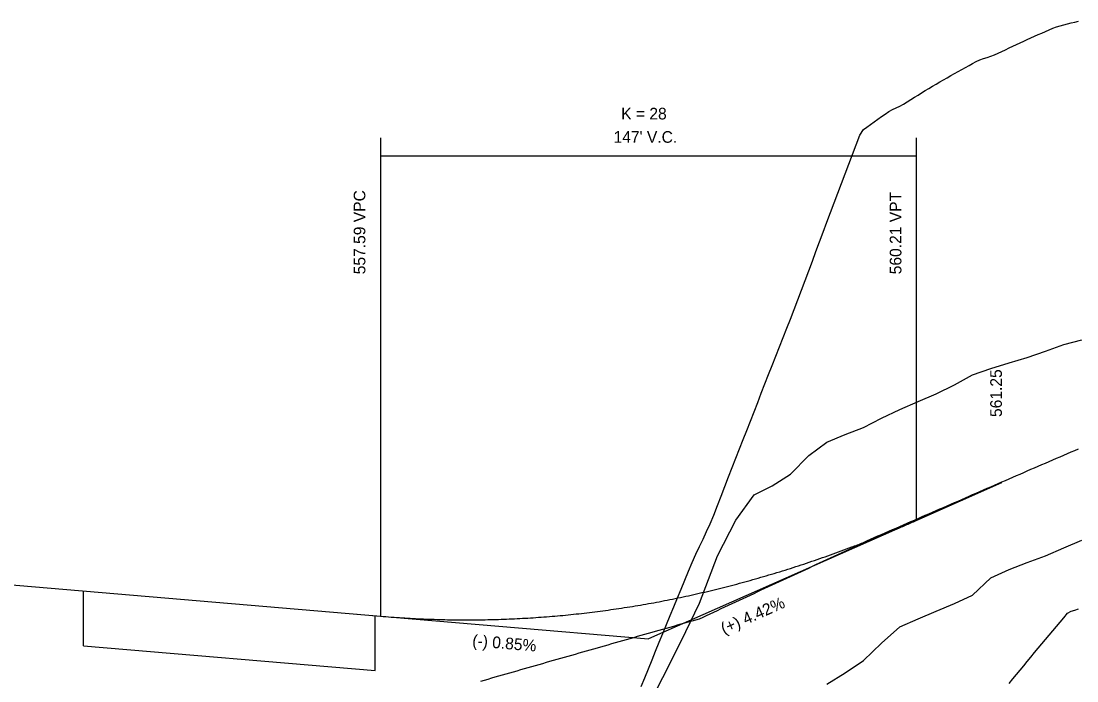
# Model space of a CAD drawing. Extents: x 1733571 to 1737171, y 1214895 to 1219895.
# Drawn here: x 1735360.8 to 1735650.6, y 1217953.6 to 1218134.6 of the extents above; entities that cross this region are included whole.
import ezdxf

# ---------------------------------------------------------------- set-up
doc = ezdxf.new("R2010")
doc.units = 0
for name, color, linetype in [('RD_DDB_GradeTX', 7, 'Continuous'), ('RD_DDB_Profile_EX', 7, 'Continuous'), ('RD_DDB_Profile_Lbl', 7, 'Continuous'), ('RD_DDB_Profile_PR', 7, 'Continuous'), ('RD_DDB_StripGrade', 7, 'Continuous'), ('RD_DDB_VCLbl', 7, 'Continuous'), ('RD_PD_Bridge', 7, 'Continuous'), ('RD_Sketch1', 7, 'Continuous'), ('RD_Sketch2', 7, 'Continuous'), ('RD_Sketch3', 7, 'Continuous'), ('RD_Sketch4', 7, 'Continuous')]:
    doc.layers.add(name, color=color, linetype=linetype)

msp = doc.modelspace()

# ---------------------------------------------------------------- linework, layer by layer
at = {"layer": 'RD_DDB_GradeTX'}
for p in [(1735608.3751, 1217998.43559), (1735450.90416, 1217972.09558)]:
    msp.add_line(p, (1735533.0087, 1217965.12394), dxfattribs=at)
at = {"layer": 'RD_DDB_Profile_EX'}
for points in [[(1735603.9887, 1217996.85951), (1735604.9887, 1217997.29438), (1735605.9887, 1217997.72923), (1735606.9887, 1217998.16405), (1735607.9887, 1217998.59884), (1735608.9887, 1217999.03361), (1735609.9887, 1217999.46835), (1735610.9887, 1217999.90307), (1735611.9887, 1218000.33775), (1735612.9887, 1218000.77242), (1735613.9887, 1218001.20705), (1735614.9887, 1218001.64166), (1735615.9887, 1218002.07624), (1735616.9887, 1218002.5108), (1735617.9887, 1218002.94533), (1735618.9887, 1218003.37983), (1735619.9887, 1218003.83148), (1735620.9887, 1218004.28324), (1735621.9887, 1218004.71734), (1735622.9887, 1218005.15135), (1735623.9887, 1218005.58528), (1735624.9887, 1218006.01911), (1735625.9887, 1218006.45286), (1735626.9887, 1218006.88651), (1735627.9887, 1218007.32008), (1735628.9887, 1218007.75356), (1735629.9887, 1218008.18695), (1735630.9887, 1218008.62024), (1735631.9887, 1218009.05345), (1735632.9887, 1218009.48657), (1735633.9887, 1218009.91959), (1735634.9887, 1218010.35253), (1735635.9887, 1218010.78538), (1735636.9887, 1218011.21813), (1735637.9887, 1218011.6508), (1735638.9887, 1218012.08337), (1735639.9887, 1218012.51585), (1735640.9887, 1218012.94824), (1735641.9887, 1218013.38054), (1735642.9887, 1218013.81275), (1735643.9887, 1218014.24487), (1735644.9887, 1218014.67689), (1735645.9887, 1218015.11698), (1735646.9887, 1218015.54701), (1735647.9887, 1218015.97849), (1735648.9887, 1218016.41013), (1735649.9887, 1218016.84161), (1735650.9887, 1218017.27294)], [(1735503.9887, 1217958.42449), (1735504.9887, 1217958.70923), (1735505.9887, 1217958.99392), (1735506.9887, 1217959.27855), (1735507.9887, 1217959.56313), (1735508.9887, 1217959.84766), (1735509.9887, 1217960.13213), (1735510.9887, 1217960.41655), (1735511.9887, 1217960.70091), (1735512.9887, 1217960.98522), (1735513.9887, 1217961.26948), (1735514.9887, 1217961.55368), (1735515.9887, 1217961.83783), (1735516.9887, 1217962.12193), (1735517.9887, 1217962.40597), (1735518.9887, 1217962.68995), (1735519.9887, 1217962.97388), (1735520.9887, 1217963.25776), (1735521.9887, 1217963.54927), (1735522.9887, 1217963.8496), (1735523.9887, 1217964.14087), (1735524.9887, 1217964.42442), (1735525.9887, 1217964.70789), (1735526.9887, 1217964.99128), (1735527.9887, 1217965.27459), (1735528.9887, 1217965.55782), (1735529.9887, 1217965.84097), (1735530.9887, 1217966.12404), (1735531.9887, 1217966.40703), (1735532.9887, 1217966.68993), (1735533.9887, 1217966.97276), (1735534.9887, 1217967.2555), (1735535.9887, 1217967.53816), (1735536.9887, 1217967.82074), (1735537.9887, 1217968.10324), (1735538.9887, 1217968.38565), (1735539.9887, 1217968.66799), (1735540.9887, 1217968.95024), (1735541.9887, 1217969.23241), (1735542.9887, 1217969.5145), (1735543.9887, 1217969.79651), (1735544.9887, 1217970.07843), (1735545.9887, 1217970.36027), (1735546.9887, 1217970.64295), (1735547.9887, 1217971.10173), (1735548.9887, 1217971.56844), (1735549.9887, 1217972.03507), (1735550.9887, 1217972.50163), (1735551.9887, 1217972.96811), (1735552.9887, 1217973.43451), (1735553.9887, 1217973.90084), (1735554.9887, 1217974.36709), (1735555.9887, 1217974.83326), (1735556.9887, 1217975.29936), (1735557.9887, 1217975.76537), (1735558.9887, 1217976.23131), (1735559.9887, 1217976.69717), (1735560.9887, 1217977.16296), (1735561.9887, 1217977.62866), (1735562.9887, 1217978.09429), (1735563.9887, 1217978.55984), (1735564.9887, 1217979.02531), (1735565.9887, 1217979.4907), (1735566.9887, 1217979.95601), (1735567.9887, 1217980.42125), (1735568.9887, 1217980.8864), (1735569.9887, 1217981.35148), (1735570.9887, 1217981.80865), (1735571.9887, 1217982.25444), (1735572.9887, 1217982.71922), (1735573.9887, 1217983.18437), (1735574.9887, 1217983.64948), (1735575.9887, 1217984.11454), (1735576.9887, 1217984.57955), (1735577.9887, 1217985.04451), (1735578.9887, 1217985.50941), (1735579.9887, 1217985.97427), (1735580.9887, 1217986.43908), (1735581.9887, 1217986.90383), (1735582.9887, 1217987.36853), (1735583.9887, 1217987.83319), (1735584.9887, 1217988.29779), (1735585.9887, 1217988.76234), (1735586.9887, 1217989.22684), (1735587.9887, 1217989.69128), (1735588.9887, 1217990.15568), (1735589.9887, 1217990.62002), (1735590.9887, 1217991.08431), (1735591.9887, 1217991.54855), (1735592.9887, 1217992.01274), (1735593.9887, 1217992.47687), (1735594.9887, 1217992.93966), (1735595.9887, 1217993.37963), (1735596.9887, 1217993.8147), (1735597.9887, 1217994.24975), (1735598.9887, 1217994.68477), (1735599.9887, 1217995.11977), (1735600.9887, 1217995.55474), (1735601.9887, 1217995.98969), (1735602.9887, 1217996.42461), (1735603.9887, 1217996.85951)], [(1735486.9887, 1217953.55972), (1735487.9887, 1217953.84421), (1735488.9887, 1217954.1287), (1735489.9887, 1217954.41319), (1735490.9887, 1217954.69768), (1735491.9887, 1217954.98217), (1735492.9887, 1217955.26666), (1735493.9887, 1217955.55115), (1735494.9887, 1217955.83564), (1735495.9887, 1217956.12013), (1735496.9887, 1217956.41204), (1735497.9887, 1217956.7132), (1735498.9887, 1217956.99999), (1735499.9887, 1217957.28499), (1735500.9887, 1217957.56995), (1735501.9887, 1217957.85485), (1735502.9887, 1217958.13969), (1735503.9887, 1217958.42449)]]:
    msp.add_lwpolyline(points, dxfattribs=at)
at = {"layer": 'RD_DDB_Profile_PR'}
for p, q in [((1735606.5087, 1217997.61065), (1735630.0087, 1218007.99755)), ((1735355.0087, 1217980.23823), (1735459.5087, 1217971.36496))]:
    msp.add_line(p, q, dxfattribs=at)
msp.add_spline([(1735459.5087, 1217971.36496), (1735462.4487, 1217971.13081), (1735465.3887, 1217970.92764), (1735468.3287, 1217970.75545), (1735471.2687, 1217970.61425), (1735474.2087, 1217970.50403), (1735477.1487, 1217970.42479), (1735480.0887, 1217970.37654), (1735483.0287, 1217970.35926), (1735485.9687, 1217970.37297), (1735488.9087, 1217970.41766), (1735491.8487, 1217970.49333), (1735494.7887, 1217970.59999), (1735497.7287, 1217970.73762), (1735500.6687, 1217970.90624), (1735503.6087, 1217971.10584), (1735506.5487, 1217971.33643), (1735509.4887, 1217971.59799), (1735512.4287, 1217971.89054), (1735515.3687, 1217972.21407), (1735518.3087, 1217972.56858), (1735521.2487, 1217972.95407), (1735524.1887, 1217973.37055), (1735527.1287, 1217973.81801), (1735530.0687, 1217974.29645), (1735533.0087, 1217974.80587), (1735535.9487, 1217975.34628), (1735538.8887, 1217975.91766), (1735541.8287, 1217976.52003), (1735544.7687, 1217977.15338), (1735547.7087, 1217977.81772), (1735550.6487, 1217978.51303), (1735553.5887, 1217979.23933), (1735556.5287, 1217979.99661), (1735559.4687, 1217980.78487), (1735562.4087, 1217981.60412), (1735565.3487, 1217982.45435), (1735568.2887, 1217983.33555), (1735571.2287, 1217984.24775), (1735574.1687, 1217985.19092), (1735577.1087, 1217986.16507), (1735580.0487, 1217987.17021), (1735582.9887, 1217988.20633), (1735585.9287, 1217989.27343), (1735588.8687, 1217990.37152), (1735591.8087, 1217991.50058), (1735594.7487, 1217992.66063), (1735597.6887, 1217993.85166), (1735600.6287, 1217995.07367), (1735603.5687, 1217996.32667), (1735606.5087, 1217997.61065)], degree=3, dxfattribs=at)
at = {"layer": 'RD_DDB_VCLbl'}
for p, q in [((1735459.5087, 1218102.61065), (1735459.5087, 1217971.36496)), ((1735606.5087, 1218102.61065), (1735606.5087, 1217997.61065)), ((1735459.5087, 1218097.61065), (1735606.5087, 1218097.61065))]:
    msp.add_line(p, q, dxfattribs=at)
at = {"layer": 'RD_PD_Bridge'}
for p, q in [((1735378.0087, 1217963.23129), (1735378.0087, 1217978.28526)), ((1735458.0087, 1217956.43835), (1735458.0087, 1217971.49232)), ((1735378.0087, 1217963.23129), (1735458.0087, 1217956.43835))]:
    msp.add_line(p, q, dxfattribs=at)
at = {"layer": 'RD_Sketch1'}
for points in [[(1735605.9887, 1218113.71216), (1735606.9887, 1218114.32618), (1735607.9887, 1218114.93548), (1735608.9887, 1218115.54006), (1735609.9887, 1218116.13991), (1735610.9887, 1218116.73504), (1735611.9887, 1218117.32546), (1735612.9887, 1218117.91115), (1735613.9887, 1218118.49211), (1735614.9887, 1218119.06836), (1735615.9887, 1218119.63988), (1735616.9887, 1218120.20669), (1735617.9887, 1218120.76876), (1735618.9887, 1218121.32612), (1735619.9887, 1218121.87875), (1735620.9887, 1218122.42666), (1735621.9887, 1218122.96985), (1735622.9887, 1218123.50831), (1735623.9887, 1218123.9502), (1735624.9887, 1218124.29634), (1735625.9887, 1218124.63774), (1735626.9887, 1218124.97439), (1735627.9887, 1218125.30631), (1735628.9887, 1218125.76265), (1735629.9887, 1218126.25346), (1735630.9887, 1218126.73942), (1735631.9887, 1218127.22053), (1735632.9887, 1218127.6968), (1735633.9887, 1218128.16821), (1735634.9887, 1218128.63478), (1735635.9887, 1218129.0965), (1735636.9887, 1218129.55336), (1735637.9887, 1218130.00538), (1735638.9887, 1218130.45255), (1735639.9887, 1218130.89487), (1735640.9887, 1218131.33234), (1735641.9887, 1218131.76496), (1735642.9887, 1218132.19273), (1735643.9887, 1218132.61565), (1735644.9887, 1218133.03372), (1735645.9887, 1218133.29717), (1735646.9887, 1218133.56553), (1735647.9887, 1218133.82904), (1735648.9887, 1218134.08771), (1735649.9887, 1218134.34152), (1735650.9887, 1218134.59049)], [(1735530.9887, 1217952.05982), (1735531.9887, 1217954.49408), (1735532.9887, 1217956.92808), (1735533.9887, 1217959.36181), (1735534.9887, 1217961.79527), (1735535.9887, 1217964.22846), (1735536.9887, 1217966.66138), (1735537.9887, 1217969.09403), (1735538.9887, 1217971.52641), (1735539.9887, 1217973.95851), (1735540.9887, 1217976.39034), (1735541.9887, 1217978.82189), (1735542.9887, 1217981.25317), (1735543.9887, 1217983.68417), (1735544.9887, 1217986.11489), (1735545.9887, 1217988.36446), (1735546.9887, 1217990.44829), (1735547.9887, 1217992.53127), (1735548.9887, 1217994.61339), (1735549.9887, 1217996.69465), (1735550.9887, 1217999.07523), (1735551.9887, 1218001.69591), (1735552.9887, 1218004.31582), (1735553.9887, 1218006.93496), (1735554.9887, 1218009.55334), (1735555.9887, 1218012.14286), (1735556.9887, 1218014.69313), (1735557.9887, 1218017.24272), (1735558.9887, 1218019.79163), (1735559.9887, 1218022.33986), (1735560.9887, 1218024.88741), (1735561.9887, 1218027.43428), (1735562.9887, 1218029.98047), (1735563.9887, 1218032.52598), (1735564.9887, 1218035.07081), (1735565.9887, 1218037.61496), (1735566.9887, 1218040.15842), (1735567.9887, 1218042.7012), (1735568.9887, 1218045.24329), (1735569.9887, 1218047.7847), (1735570.9887, 1218050.32542), (1735571.9887, 1218052.86545), (1735572.9887, 1218055.4749), (1735573.9887, 1218058.13616), (1735574.9887, 1218060.79675), (1735575.9887, 1218063.45669), (1735576.9887, 1218066.11597), (1735577.9887, 1218068.77459), (1735578.9887, 1218071.43254), (1735579.9887, 1218074.08984), (1735580.9887, 1218076.74647), (1735581.9887, 1218079.40244), (1735582.9887, 1218082.05775), (1735583.9887, 1218084.71239), (1735584.9887, 1218087.36636), (1735585.9887, 1218090.01967), (1735586.9887, 1218092.67231), (1735587.9887, 1218095.32428), (1735588.9887, 1218097.97559), (1735589.9887, 1218100.62622), (1735590.9887, 1218103.27618), (1735591.9887, 1218104.88004), (1735592.9887, 1218105.48353), (1735593.9887, 1218106.21809), (1735594.9887, 1218106.94807), (1735595.9887, 1218107.67347), (1735596.9887, 1218108.3943), (1735597.9887, 1218109.11055), (1735598.9887, 1218109.82222), (1735599.9887, 1218110.34776), (1735600.9887, 1218110.80972), (1735601.9887, 1218111.26707), (1735602.9887, 1218111.84178), (1735603.9887, 1218112.46996), (1735604.9887, 1218113.09342), (1735605.9887, 1218113.71216)]]:
    msp.add_lwpolyline(points, dxfattribs=at)
at = {"layer": 'RD_Sketch2'}
msp.add_lwpolyline([(1735631.9887, 1217952.93139), (1735632.9887, 1217954.13704), (1735633.9887, 1217955.34216), (1735634.9887, 1217956.54673), (1735635.9887, 1217957.75075), (1735636.9887, 1217958.95424), (1735637.9887, 1217960.15717), (1735638.9887, 1217961.35957), (1735639.9887, 1217962.56142), (1735640.9887, 1217963.76272), (1735641.9887, 1217964.96348), (1735642.9887, 1217966.16369), (1735643.9887, 1217967.36335), (1735644.9887, 1217968.56247), (1735645.9887, 1217969.76104), (1735646.9887, 1217970.95907), (1735647.9887, 1217972.15654), (1735648.9887, 1217972.70381), (1735649.9887, 1217973.02213), (1735650.9887, 1217973.33989)], dxfattribs=at)
at = {"layer": 'RD_Sketch3'}
msp.add_lwpolyline([(1735531.9887, 1217944.98611), (1735536.9887, 1217954.56098), (1735541.9887, 1217964.55168), (1735546.9887, 1217974.9236), (1735551.9887, 1217987.88939), (1735556.9887, 1217997.6888), (1735561.9887, 1218004.65939), (1735566.9887, 1218007.13947), (1735571.9887, 1218010.32328), (1735576.9887, 1218015.45904), (1735581.9887, 1218019.11328), (1735586.9887, 1218021.16106), (1735591.9887, 1218023.09618), (1735596.9887, 1218025.63923), (1735601.9887, 1218028.0622), (1735606.9887, 1218030.26806), (1735611.9887, 1218032.35949), (1735616.9887, 1218034.81429), (1735621.9887, 1218037.55819), (1735626.9887, 1218039.27961), (1735631.9887, 1218040.88318), (1735636.9887, 1218042.36889), (1735641.9887, 1218044.07053), (1735646.9887, 1218045.91101), (1735651.9887, 1218047.15381)], dxfattribs=at)
at = {"layer": 'RD_Sketch4'}
msp.add_lwpolyline([(1735581.9887, 1217952.69925), (1735586.9887, 1217955.84089), (1735591.9887, 1217959.17242), (1735596.9887, 1217963.9224), (1735601.9887, 1217968.41083), (1735606.9887, 1217970.60741), (1735611.9887, 1217972.7506), (1735616.9887, 1217974.8404), (1735621.9887, 1217977.15522), (1735626.9887, 1217981.86321), (1735631.9887, 1217984.17949), (1735636.9887, 1217986.05709), (1735641.9887, 1217987.9002), (1735646.9887, 1217990.10265), (1735651.9887, 1217992.22976)], dxfattribs=at)

# ---------------------------------------------------------------- texts
at = {"layer": 'RD_DDB_GradeTX'}
for s, rotation, p in [('(+) 4.42%', 23.8452363, (1735553.72964, 1217966.33115)), ('(-) 0.85%', 355.1465568, (1735484.5834, 1217963.14049))]:
    msp.add_text(s, height=3.2, rotation=rotation, dxfattribs=at).set_placement(p)
at = {"layer": 'RD_DDB_Profile_Lbl'}
msp.add_text('561.25', height=3.2, rotation=90, dxfattribs=at).set_placement((1735630.0087, 1218025.99755))
at = {"layer": 'RD_DDB_StripGrade'}
for s, p in [('557.59 VPC', (1735455.32412, 1218065.1457)), ('560.21 VPT', (1735602.43193, 1218065.1457))]:
    msp.add_text(s, height=3.2, rotation=90, dxfattribs=at).set_placement(p)
at = {"layer": 'RD_DDB_VCLbl'}
for s, p in [('K = 28', (1735525.52987, 1218107.61335)), ("147' V.C.", (1735523.444, 1218101.21335))]:
    msp.add_text(s, height=3.2, dxfattribs=at).set_placement(p)

doc.saveas('drawing.dxf')
